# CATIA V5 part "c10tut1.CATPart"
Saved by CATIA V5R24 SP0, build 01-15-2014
Part number: c10tut1
Bounding box of the stored display mesh (mm): x -88.579 to 88.579, y -88.579 to 151.815, z -258.54 to 20
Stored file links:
  D:\KAVITA\CATIA V5-6R2014 Project_ Kavita\CATIA V5-6R2014_partfiles\Tutorials\c10_catia_v5-6r2014_tut\c10tut1.CATPart
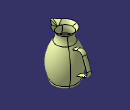
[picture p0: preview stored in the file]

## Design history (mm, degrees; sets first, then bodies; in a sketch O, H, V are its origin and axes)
Body1 (main body)
  Sketch1 on xy-plane, origin (0, 0, 0), H (1, 0, 0), V (0, 1, 0)
    circle A1 centre (0, 0) radius 45
    point P1 (-5, -44.7214)
    point P2 (5, -44.7214)
    radius A1 = 45
    distance P2 P1 = 10
    distance V P1 = 5
    coincidence: P1 A1, P2 A1
  Plane1: type Offset, RefPlane xy-plane, Offset 20
  Sketch2 on Plane1, origin (0, 0, 20), H (1, 0, 0), V (0, 1, 0)
    arc A1 centre (0, 0) radius 60 from (30.5123, -51.6623) to (-30.5123, -51.6623) ccw
    line L1 (-30.5123, -51.6623) -> (-7.9335, -81.0876)
    point P1 (0, -91.4268)
    line L2 (7.9335, -81.0876) -> (30.5123, -51.6623)
    arc A2 centre (0, -75) radius 10 from (-7.9335, -81.0876) to (7.9335, -81.0876) ccw
    point P4 (0, -75)
    radius A1 = 60
    angle L1 L2 = 75
    radius A2 = 10
    distance P4 H = 75
    coincidence: P1 V, L1 P1, L2 P1, P4 V
    tangency: A2 L1, A2 L2
  Line1: type PtPt, FirstPoint Sketch1.P2, SecondPoint vertex [element of Sketch2 | element of Sketch2]
  Loft1: Sections (Sketch1.A1; Sketch2), Guides Line1
  Sketch3 on yz-plane, origin (0, 0, 0), H (0, 1, 0), V (0, 0, 1)
    axis line L1 (0, 49.2285) -> (0, -442.7765)
    point P1 (0, 49.2285)
    arc A1 centre (-106.3963, -163.4174) radius 195 from (70, -246.5398) to (52.2275, -50) ccw
    point P4 (70, -246.5398)
    point P5 (52.2275, -50)
    arc A2 centre (96.9675, -18.0105) radius 55 from (45, 0) to (52.2275, -50) ccw
    point P7 (52.2275, -50)
    point P8 (45, 0)
    line L2 (54, -258.5398) -> (64, -258.5398)
    point P9 (54, -258.5398)
    point P10 (64, -258.5398)
    arc A3 centre (64, -251.0398) radius 7.5 from (64, -258.5398) to (70, -246.5398) ccw
    point P12 (64, -258.5398)
    arc A4 centre (0, -425) radius 175 from (54, -258.5398) to (0, -250) ccw
    point P13 (0, -425)
    point P14 (0, -250)
    radius A2 = 55
    radius A1 = 195
    radius A3 = 7.5
    length L2 = 10
    radius A4 = 175
    distance P14 H = 250
    radius about axis P4 L1 = 70
    radius about axis P9 L1 = 54
    radius about axis P8 L1 = 45
    distance P5 H = 50
    coincidence: P1 V, P7 A1, P7 P5, P10 P12, P13 L1, P14 L1, P8 H
    tangency: A2 A1, A3 L2
    vertical: L1 V
    horizontal: L2 H
  Revol1: Element1 Sketch3, Angle1 360
  Sketch4 on yz-plane, origin (0, 0, 0), H (0, 1, 0), V (0, 0, 1)
    point P1 (35.2741, -74.8693)
    line L1 (35.2741, -74.8693) -> (86.9572, -56.0582)
    line L2 (119, -71) -> (145.5066, -143.8262)
    line L3 (130.5647, -175.869) -> (63.8466, -200.1524)
    arc A1 centre (95.5077, -79.5505) radius 25 from (86.9572, -56.0582) to (119, -71) cw
    point P4 (119, -71)
    arc A2 centre (122.0142, -152.3767) radius 25 from (145.5066, -143.8262) to (130.5647, -175.869) cw
    radius A1 = 25
    radius A2 = 25
    length L2 = 77.5
    length L1 = 55
    angle H L1 = 20
    distance P4 V = 119
    distance P4 H = 71
    length L3 = 71
    perpendicularity: L2 L1
    parallelism: L3 L1
    tangency: A1 L1, A1 L2, A2 L2, A2 L3
  Plane2: type Normal, Curve Sketch4, RefPoint Sketch4.P1
  Sketch5 on Plane2, origin (0, 7.0853, 2.5788), H (1, 0, 0), V (0, -0.342, 0.9397)
    point P1 (0, -82.4186)
    ellipse A1 centre (0, -82.4186) semi-axes 12.5, 5 rotation 0
    reference projected point E1 (0, -82.4186) from Sketch4.P1
    "Radius" A1 = 5
    "Radius" A1 = 12.5
    horizontal: A1 H
    coincidence: P1 E1
  Sweep1: type Unspec, Profile Sketch5, Guide Sketch4
  Split1: ToCut Sweep1, Cutting Revol1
